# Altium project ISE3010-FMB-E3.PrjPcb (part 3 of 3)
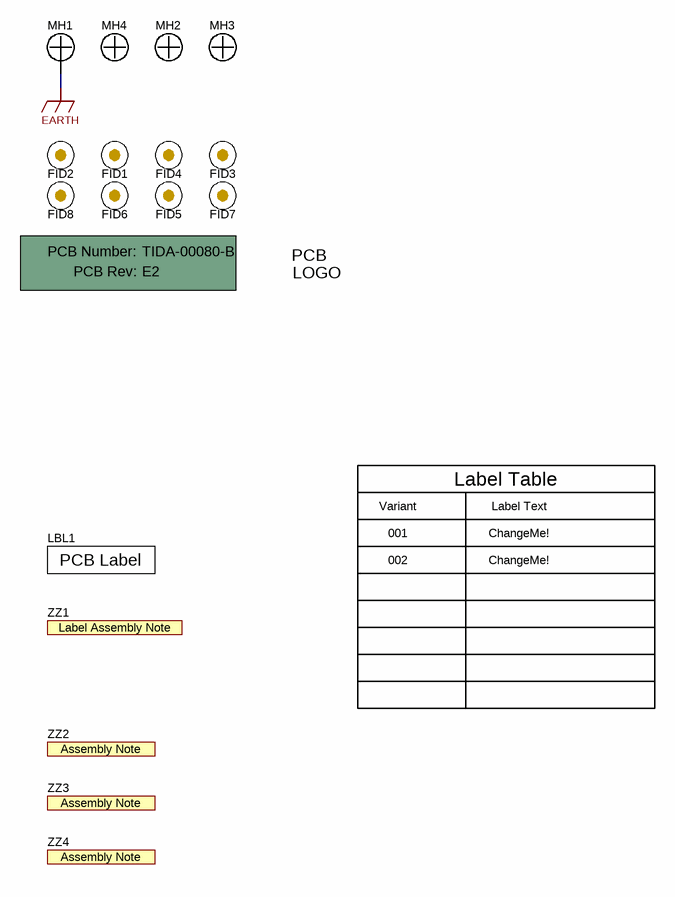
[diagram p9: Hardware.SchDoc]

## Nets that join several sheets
+1.2V: Power Supply (C145.1 FB4.2), FPGA Power (12 pins)
+1.8V: Power Supply (C108.1 TP10.1 U31.1), FPGA CLOCK_USB (FB3.1)
+3.3V_DVDD: Power Supply (10 pins), SDM OP Filtering (31 pins), Control card connector (7 pins), FPGA Power (49 pins), FPGA CLOCK_USB (54 pins), DAC (18 pins)
+4.096VREF: SDM OP Filtering (C27.1 TP1.1 U12.2), DAC (8 pins)
+5V_AVDD: SDM OP Filtering (6 pins), DAC (24 pins)
+5V_CNTL: Power Supply (8 pins), SDM OP Filtering (FB1.1), Control card connector (14 pins)
DGND: Power Supply (43 pins), SDM OP Filtering (51 pins), Control card connector (36 pins), FPGA Power (58 pins), FPGA CLOCK_USB (69 pins), DAC (69 pins)
EARTH: FPGA CLOCK_USB (J3.6 J3.7 J3.8 J3.9), Hardware (MH1.1)
CLKN_CH_U: Control card connector (J1.9), FPGA CLOCK_USB (R47.1)
CLKN_CH_V: Control card connector (J1.13), FPGA CLOCK_USB (R51.1)
CLKN_CH_W: Control card connector (J1.17), FPGA CLOCK_USB (R55.1)
CLKN_U_PH: Control card connector (J1.22), FPGA CLOCK_USB (R59.1)
CLKN_V_PH: Control card connector (J1.26), FPGA CLOCK_USB (R63.1)
CLKN_VDC: Control card connector (J1.34), FPGA CLOCK_USB (U20.47)
CLKN_W_PH: Control card connector (J1.30), FPGA CLOCK_USB (R67.1)
CLKP_CH_U: Control card connector (J1.10 J5.109 R23.1), FPGA Power (U20.15), FPGA CLOCK_USB (C60.1 R46.1)
CLKP_CH_V: Control card connector (J1.14 J5.105 R21.1), FPGA Power (U20.14), FPGA CLOCK_USB (C56.1 R50.1)
CLKP_CH_W: Control card connector (J1.18 J5.101 R18.1), FPGA Power (U20.12), FPGA CLOCK_USB (C42.1 R54.1)
CLKP_U_PH: Control card connector (J1.21 J5.110 R160.2), FPGA Power (U20.23), FPGA CLOCK_USB (C82.1 R58.1)
CLKP_V_PH: Control card connector (J1.25 J5.106 R161.2), FPGA Power (U20.21), FPGA CLOCK_USB (C69.1 R62.1)
CLKP_VDC: Control card connector (J1.33 J5.78 R163.2), FPGA CLOCK_USB (U20.48)
CLKP_W_PH: Control card connector (J1.29 J5.102 R162.2), FPGA Power (U20.17), FPGA CLOCK_USB (C62.1 R66.1)
DOUTN_CH_U: Control card connector (J1.7), FPGA CLOCK_USB (R45.1)
DOUTN_CH_V: Control card connector (J1.11), FPGA CLOCK_USB (R49.1)
DOUTN_CH_W: Control card connector (J1.15), FPGA CLOCK_USB (R53.1)
DOUTN_U_PH: Control card connector (J1.20), FPGA CLOCK_USB (R57.1)
DOUTN_V_PH: Control card connector (J1.24), FPGA CLOCK_USB (R61.1)
DOUTN_VDC: Control card connector (J1.32), FPGA CLOCK_USB (U20.45)
DOUTN_W_PH: Control card connector (J1.28), FPGA CLOCK_USB (R65.1)
DOUTP_CH_U: SDM OP Filtering (R24.2), Control card connector (J1.8 J5.107), FPGA CLOCK_USB (R44.1)
DOUTP_CH_V: SDM OP Filtering (R14.2), Control card connector (J1.12 J5.103), FPGA CLOCK_USB (R48.1)
DOUTP_CH_W: SDM OP Filtering (R13.2), Control card connector (J1.16 J5.99), FPGA CLOCK_USB (R52.1)
DOUTP_U_PH: SDM OP Filtering (R39.2), Control card connector (J1.19 J5.108), FPGA CLOCK_USB (R56.1)
DOUTP_V_PH: SDM OP Filtering (R37.2), Control card connector (J1.23 J5.104), FPGA CLOCK_USB (R60.1)
DOUTP_VDC: SDM OP Filtering (R8.2), Control card connector (J1.31 J5.76), FPGA CLOCK_USB (U20.46)
DOUTP_W_PH: SDM OP Filtering (R38.2), Control card connector (J1.27 J5.100), FPGA CLOCK_USB (R64.1)
FPGA_DAC_ENABLE-3: FPGA Power (U20.10), DAC (U25.15)
FPGA_DAC_ENABLE-4: FPGA Power (U20.9), DAC (U28.15)
FPGA_DAC_SCK: FPGA Power (R179.1), DAC (U25.10 U28.10)
FPGA_DAC_SDI: FPGA Power (R175.1), DAC (U25.11 U28.11)
FPGA_DAC_SYNC: FPGA Power (U20.7), DAC (U25.9 U28.9)
FPGA_LDAC: FPGA Power (U20.8), DAC (U25.16 U28.16)
GPIO1_FPGA: FPGA Power (U20.27), DAC (J15.7)
GPIO2_FPGA: FPGA Power (U20.26), DAC (J15.8)
GPIO3_FPGA: FPGA Power (U20.24), DAC (J15.10)
I2C_SCL: Control card connector (J4.161), FPGA CLOCK_USB (R208.2 U22.10)
I2C_SDA: Control card connector (J4.160), FPGA CLOCK_USB (R207.2 U22.9)
MCU_DAC_ENABLE-1: Control card connector (J4.132), DAC (U16.15)
MCU_DAC_ENABLE-2: Control card connector (J4.127), DAC (U21.15)
MCU_DAC_SCK: Control card connector (R165.1), DAC (U16.10 U21.10)
MCU_DAC_SDI: Control card connector (R164.1), DAC (U16.11 U21.11)
MCU_DAC_SYNC: Control card connector (J4.133), DAC (U16.9 U21.9)
MCU_LDAC: Control card connector (J4.131), DAC (U16.16 U21.16)
PH_U_ADCIN: SDM OP Filtering (C31.2 U15.2 U15.6), Control card connector (J5.12)
PH_V_ADCIN: SDM OP Filtering (C29.2 U13.2 U13.6), Control card connector (J5.18)
PH_W_ADCIN: SDM OP Filtering (C30.2 U14.2 U14.6), Control card connector (J5.14)
PWM_1: FPGA CLOCK_USB (R94.1), DAC (J12.1)
PWM_2: FPGA CLOCK_USB (R99.1), DAC (J12.3)
PWM_3: FPGA CLOCK_USB (R105.1), DAC (J12.5)
PWM_4: FPGA CLOCK_USB (R106.1), DAC (J12.7)
PWM_5: FPGA CLOCK_USB (R112.1), DAC (J12.9)
PWM_6: FPGA CLOCK_USB (R120.1), DAC (J12.11)
PWM_SYNC: Control card connector (J2.2 J4.121 R159.1), FPGA CLOCK_USB (R9.2)
PWM_SYNC_FPGA: FPGA Power (U20.30), DAC (J15.5)
S0_CLK_GEN: Control card connector (J4.154), FPGA CLOCK_USB (R86.1 U22.1)
S1_CLK_GEN: Control card connector (J4.156), FPGA CLOCK_USB (R88.1 U22.2)
SC_ALARM_FPGA: FPGA Power (U20.29), DAC (J15.6)
SH_U_ADCIN: SDM OP Filtering (C16.2 U8.2 U8.6), Control card connector (J5.9)
SH_V_ADCIN: SDM OP Filtering (C8.2 U3.2 U3.6), Control card connector (J5.11)
SH_W_ADCIN: SDM OP Filtering (C7.2 U2.2 U2.6), Control card connector (J5.15)
SPI_CLK_FPGA: FPGA Power (U20.33), DAC (J15.3)
SPI_MISO_FPGA: FPGA Power (U20.34), DAC (J15.1)
SPI_MOSI_FPGA: FPGA Power (U20.35), DAC (J15.2)
SPI_STE_FPGA: FPGA Power (U20.32), DAC (J15.4)
USB_RS232_RXD: FPGA Power (U20.5), FPGA CLOCK_USB (U7.25)
USB_RS232_TXD: FPGA Power (U20.2), FPGA CLOCK_USB (U7.26)
VDC_ADCIN: SDM OP Filtering (C6.2 U1.2 U1.6), Control card connector (J5.21)

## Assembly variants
001: not fitted C15 C17 C20 C22 C27 C63 C66 C83 C86 C88 C92 C96 C99 C101 C103 C104 C108 C123 C124 C126 C127 C128 C129 C130 C131 C132 C133 C134 C137 C138 C140 C141 C142 C143 C144 C145 C147 C148 C149 C151 C152 C154 C157 C158 C159 C160 C161 C162 C163 C165 C169 C170 C171 C173 C175 C176 C178 D1 D2 D3 D9 D13 FB2 FB3 FB4 FB5 FID1 FID2 FID4 J3 J11 R22 R29 R30 R44 R45 R46 R47 R48 R49 R50 R51 R52 R53 R54 R55 R56 R57 R58 R59 R60 R61 R62 R63 R64 R65 R66 R67 R75 R76 R78 R81 R82 R89 R90 R94 R95 R97 R99 R100 R101 R103 R105 R106 R110 R111 R112 R116 R119 R120 R121 R124 R125 R127 R128 R129 R133 R134 R136 R141 R144 R146 R147 R148 R152 R154 R155 R158 R166 R167 R171 R174 R175 R179 R183 R185 R187 R188 R189 R192 R194 R195 R196 R197 R199 R201 R202 R203 R205 S1 S2 S3 TP10 U7 U9 U12 U20 U27 U29 U31 U33 U35 U36 U37 Y2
